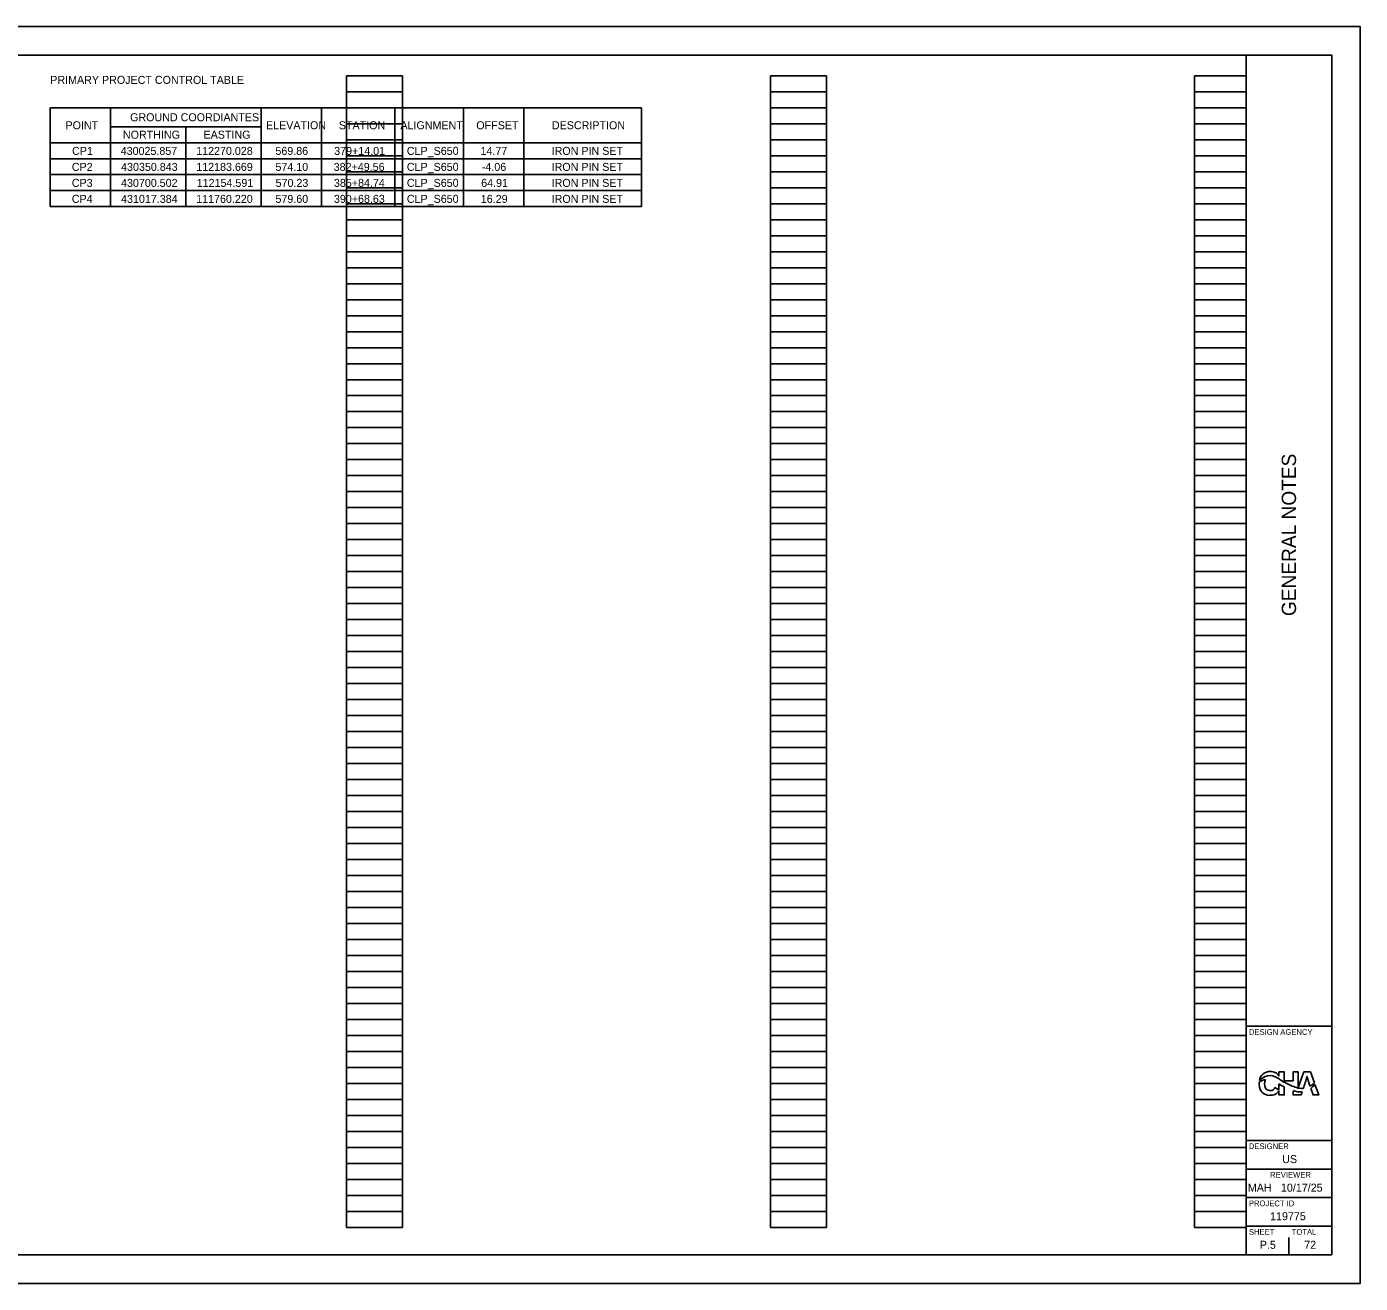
# Model space of a CAD drawing. Extents: x -7.3 to 34, y 0 to 22.
# Drawn here: x 10.66 to 34, y 0 to 22 of the extents above; entities that cross this region are included whole.
import ezdxf

# ---------------------------------------------------------------- set-up
doc = ezdxf.new("R2010")
doc.units = 0
for name, color, linetype in [('Default', 7, 'Continuous'), ('SH_Border', 7, 'Continuous'), ('SH_Cut_Line', 7, 'Continuous'), ('SH_Data', 7, 'Continuous'), ('SH_Text', 7, 'Continuous')]:
    doc.layers.add(name, color=color, linetype=linetype)

msp = doc.modelspace()

# ---------------------------------------------------------------- linework, layer by layer
at = {"layer": 'Default'}
for p, q in [((11.078, 20.578), (21.421, 20.578)), ((11.078, 20.578), (11.078, 18.849)), ((12.132, 20.578), (12.132, 18.849)), ((14.767, 20.578), (14.767, 18.849)), ((15.821, 20.578), (15.821, 18.849)), ((17.106, 20.578), (17.106, 18.849)), ((18.308, 20.578), (18.308, 18.849)), ((19.362, 20.578), (19.362, 18.849)), ((21.421, 20.578), (21.421, 18.849)), ((12.132, 20.249), (14.767, 20.249)), ((13.449, 20.249), (13.449, 18.849)), ((11.078, 19.969), (21.421, 19.969)), ((11.078, 19.689), (21.421, 19.689)), ((11.078, 19.409), (21.421, 19.409)), ((11.078, 19.129), (21.421, 19.129)), ((11.078, 18.849), (21.421, 18.849))]:
    msp.add_line(p, q, dxfattribs=at)
at = {"layer": 'SH_Border'}
for p, q in [((32, 0.5), (32, 21.5)), ((32, 4.5), (33.5, 4.5)), ((32, 2.5), (33.5, 2.5)), ((32, 2), (33.5, 2)), ((32, 1.5), (33.5, 1.5)), ((32, 1), (33.5, 1))]:
    msp.add_line(p, q, dxfattribs=at)
msp.add_lwpolyline([(1.5, 21.5), (33.5, 21.5), (33.5, 0.5), (1.5, 0.5)], close=True, dxfattribs=at)
at = {"layer": 'SH_Cut_Line'}
msp.add_lwpolyline([(0, 0), (34, 0), (34, 22), (0, 22)], close=True, dxfattribs=at)
at = {"layer": 'SH_Data'}
for p, q in [((16.26, 0.98), (16.26, 21.14)), ((16.26, 21.14), (17.24, 21.14)), ((17.24, 0.98), (17.24, 21.14)), ((23.68, 0.98), (23.68, 21.14)), ((23.68, 21.14), (24.66, 21.14)), ((24.66, 0.98), (24.66, 21.14)), ((31.1, 0.98), (31.1, 21.14)), ((31.1, 21.14), (32, 21.14)), ((32, 0.98), (32, 21.14)), ((16.26, 20.86), (17.24, 20.86)), ((23.68, 20.86), (24.66, 20.86)), ((31.1, 20.86), (32, 20.86)), ((16.26, 20.58), (17.24, 20.58)), ((23.68, 20.58), (24.66, 20.58)), ((31.1, 20.58), (32, 20.58)), ((16.26, 20.3), (17.24, 20.3)), ((23.68, 20.3), (24.66, 20.3)), ((31.1, 20.3), (32, 20.3)), ((16.26, 20.02), (17.24, 20.02)), ((23.68, 20.02), (24.66, 20.02)), ((31.1, 20.02), (32, 20.02)), ((16.26, 19.74), (17.24, 19.74)), ((23.68, 19.74), (24.66, 19.74)), ((31.1, 19.74), (32, 19.74)), ((16.26, 19.46), (17.24, 19.46)), ((23.68, 19.46), (24.66, 19.46)), ((31.1, 19.46), (32, 19.46)), ((16.26, 19.18), (17.24, 19.18)), ((23.68, 19.18), (24.66, 19.18)), ((31.1, 19.18), (32, 19.18)), ((16.26, 18.9), (17.24, 18.9)), ((23.68, 18.9), (24.66, 18.9)), ((31.1, 18.9), (32, 18.9)), ((16.26, 18.62), (17.24, 18.62)), ((23.68, 18.62), (24.66, 18.62)), ((31.1, 18.62), (32, 18.62)), ((16.26, 18.34), (17.24, 18.34)), ((23.68, 18.34), (24.66, 18.34)), ((31.1, 18.34), (32, 18.34)), ((16.26, 18.06), (17.24, 18.06)), ((23.68, 18.06), (24.66, 18.06)), ((31.1, 18.06), (32, 18.06)), ((16.26, 17.78), (17.24, 17.78)), ((23.68, 17.78), (24.66, 17.78)), ((31.1, 17.78), (32, 17.78)), ((16.26, 17.5), (17.24, 17.5)), ((23.68, 17.5), (24.66, 17.5)), ((31.1, 17.5), (32, 17.5)), ((16.26, 17.22), (17.24, 17.22)), ((23.68, 17.22), (24.66, 17.22)), ((31.1, 17.22), (32, 17.22)), ((16.26, 16.94), (17.24, 16.94)), ((23.68, 16.94), (24.66, 16.94)), ((31.1, 16.94), (32, 16.94)), ((16.26, 16.66), (17.24, 16.66)), ((23.68, 16.66), (24.66, 16.66)), ((31.1, 16.66), (32, 16.66)), ((16.26, 16.38), (17.24, 16.38)), ((23.68, 16.38), (24.66, 16.38)), ((31.1, 16.38), (32, 16.38)), ((16.26, 16.1), (17.24, 16.1)), ((23.68, 16.1), (24.66, 16.1)), ((31.1, 16.1), (32, 16.1)), ((16.26, 15.82), (17.24, 15.82)), ((23.68, 15.82), (24.66, 15.82)), ((31.1, 15.82), (32, 15.82)), ((16.26, 15.54), (17.24, 15.54)), ((23.68, 15.54), (24.66, 15.54)), ((31.1, 15.54), (32, 15.54)), ((16.26, 15.26), (17.24, 15.26)), ((23.68, 15.26), (24.66, 15.26)), ((31.1, 15.26), (32, 15.26)), ((16.26, 14.98), (17.24, 14.98)), ((23.68, 14.98), (24.66, 14.98)), ((31.1, 14.98), (32, 14.98)), ((16.26, 14.7), (17.24, 14.7)), ((23.68, 14.7), (24.66, 14.7)), ((31.1, 14.7), (32, 14.7)), ((16.26, 14.42), (17.24, 14.42)), ((23.68, 14.42), (24.66, 14.42)), ((31.1, 14.42), (32, 14.42)), ((16.26, 14.14), (17.24, 14.14)), ((23.68, 14.14), (24.66, 14.14)), ((31.1, 14.14), (32, 14.14)), ((16.26, 13.86), (17.24, 13.86)), ((23.68, 13.86), (24.66, 13.86)), ((31.1, 13.86), (32, 13.86)), ((16.26, 13.58), (17.24, 13.58)), ((23.68, 13.58), (24.66, 13.58)), ((31.1, 13.58), (32, 13.58)), ((16.26, 13.3), (17.24, 13.3)), ((23.68, 13.3), (24.66, 13.3)), ((31.1, 13.3), (32, 13.3)), ((16.26, 13.02), (17.24, 13.02)), ((23.68, 13.02), (24.66, 13.02)), ((31.1, 13.02), (32, 13.02)), ((16.26, 12.74), (17.24, 12.74)), ((23.68, 12.74), (24.66, 12.74)), ((31.1, 12.74), (32, 12.74)), ((16.26, 12.46), (17.24, 12.46)), ((23.68, 12.46), (24.66, 12.46)), ((31.1, 12.46), (32, 12.46)), ((16.26, 12.18), (17.24, 12.18)), ((23.68, 12.18), (24.66, 12.18)), ((31.1, 12.18), (32, 12.18)), ((16.26, 11.9), (17.24, 11.9)), ((23.68, 11.9), (24.66, 11.9)), ((31.1, 11.9), (32, 11.9)), ((16.26, 11.62), (17.24, 11.62)), ((23.68, 11.62), (24.66, 11.62)), ((31.1, 11.62), (32, 11.62)), ((16.26, 11.34), (17.24, 11.34)), ((23.68, 11.34), (24.66, 11.34)), ((31.1, 11.34), (32, 11.34)), ((16.26, 11.06), (17.24, 11.06)), ((23.68, 11.06), (24.66, 11.06)), ((31.1, 11.06), (32, 11.06)), ((16.26, 10.78), (17.24, 10.78)), ((23.68, 10.78), (24.66, 10.78)), ((31.1, 10.78), (32, 10.78)), ((16.26, 10.5), (17.24, 10.5)), ((23.68, 10.5), (24.66, 10.5)), ((31.1, 10.5), (32, 10.5)), ((16.26, 10.22), (17.24, 10.22)), ((23.68, 10.22), (24.66, 10.22)), ((31.1, 10.22), (32, 10.22)), ((16.26, 9.94), (17.24, 9.94)), ((23.68, 9.94), (24.66, 9.94)), ((31.1, 9.94), (32, 9.94)), ((16.26, 9.66), (17.24, 9.66)), ((23.68, 9.66), (24.66, 9.66)), ((31.1, 9.66), (32, 9.66)), ((16.26, 9.38), (17.24, 9.38)), ((23.68, 9.38), (24.66, 9.38)), ((31.1, 9.38), (32, 9.38)), ((16.26, 9.1), (17.24, 9.1)), ((23.68, 9.1), (24.66, 9.1)), ((31.1, 9.1), (32, 9.1)), ((16.26, 8.82), (17.24, 8.82)), ((23.68, 8.82), (24.66, 8.82)), ((31.1, 8.82), (32, 8.82)), ((16.26, 8.54), (17.24, 8.54)), ((23.68, 8.54), (24.66, 8.54)), ((31.1, 8.54), (32, 8.54)), ((16.26, 8.26), (17.24, 8.26)), ((23.68, 8.26), (24.66, 8.26)), ((31.1, 8.26), (32, 8.26)), ((16.26, 7.98), (17.24, 7.98)), ((23.68, 7.98), (24.66, 7.98)), ((31.1, 7.98), (32, 7.98)), ((16.26, 7.7), (17.24, 7.7)), ((23.68, 7.7), (24.66, 7.7)), ((31.1, 7.7), (32, 7.7)), ((16.26, 7.42), (17.24, 7.42)), ((23.68, 7.42), (24.66, 7.42)), ((31.1, 7.42), (32, 7.42)), ((16.26, 7.14), (17.24, 7.14)), ((23.68, 7.14), (24.66, 7.14)), ((31.1, 7.14), (32, 7.14)), ((16.26, 6.86), (17.24, 6.86)), ((23.68, 6.86), (24.66, 6.86)), ((31.1, 6.86), (32, 6.86)), ((16.26, 6.58), (17.24, 6.58)), ((23.68, 6.58), (24.66, 6.58)), ((31.1, 6.58), (32, 6.58)), ((16.26, 6.3), (17.24, 6.3)), ((23.68, 6.3), (24.66, 6.3)), ((31.1, 6.3), (32, 6.3)), ((16.26, 6.02), (17.24, 6.02)), ((23.68, 6.02), (24.66, 6.02)), ((31.1, 6.02), (32, 6.02)), ((16.26, 5.74), (17.24, 5.74)), ((23.68, 5.74), (24.66, 5.74)), ((31.1, 5.74), (32, 5.74)), ((16.26, 5.46), (17.24, 5.46)), ((23.68, 5.46), (24.66, 5.46)), ((31.1, 5.46), (32, 5.46)), ((16.26, 5.18), (17.24, 5.18)), ((23.68, 5.18), (24.66, 5.18)), ((31.1, 5.18), (32, 5.18)), ((16.26, 4.9), (17.24, 4.9)), ((23.68, 4.9), (24.66, 4.9)), ((31.1, 4.9), (32, 4.9)), ((16.26, 4.62), (17.24, 4.62)), ((23.68, 4.62), (24.66, 4.62)), ((31.1, 4.62), (32, 4.62)), ((16.26, 4.34), (17.24, 4.34)), ((23.68, 4.34), (24.66, 4.34)), ((31.1, 4.34), (32, 4.34)), ((16.26, 4.06), (17.24, 4.06)), ((23.68, 4.06), (24.66, 4.06)), ((31.1, 4.06), (32, 4.06)), ((16.26, 3.78), (17.24, 3.78)), ((23.68, 3.78), (24.66, 3.78)), ((31.1, 3.78), (32, 3.78)), ((16.26, 3.5), (17.24, 3.5)), ((23.68, 3.5), (24.66, 3.5)), ((31.1, 3.5), (32, 3.5)), ((32.75, 3.5), (32.75, 3.5)), ((16.26, 3.22), (17.24, 3.22)), ((23.68, 3.22), (24.66, 3.22)), ((31.1, 3.22), (32, 3.22)), ((16.26, 2.94), (17.24, 2.94)), ((23.68, 2.94), (24.66, 2.94)), ((31.1, 2.94), (32, 2.94)), ((16.26, 2.66), (17.24, 2.66)), ((23.68, 2.66), (24.66, 2.66)), ((31.1, 2.66), (32, 2.66)), ((16.26, 2.38), (17.24, 2.38)), ((23.68, 2.38), (24.66, 2.38)), ((31.1, 2.38), (32, 2.38)), ((16.26, 2.1), (17.24, 2.1)), ((23.68, 2.1), (24.66, 2.1)), ((31.1, 2.1), (32, 2.1)), ((16.26, 1.82), (17.24, 1.82)), ((23.68, 1.82), (24.66, 1.82)), ((31.1, 1.82), (32, 1.82)), ((16.26, 1.54), (17.24, 1.54)), ((23.68, 1.54), (24.66, 1.54)), ((31.1, 1.54), (32, 1.54)), ((16.26, 1.26), (17.24, 1.26)), ((23.68, 1.26), (24.66, 1.26)), ((31.1, 1.26), (32, 1.26)), ((16.26, 0.98), (17.24, 0.98)), ((23.68, 0.98), (24.66, 0.98)), ((31.1, 0.98), (32, 0.98)), ((32.75, 0.5), (32.75, 0.8)), ((32.375, 0.675), (32.375, 0.675))]:
    msp.add_line(p, q, dxfattribs=at)
at = {"layer": 'SH_Text'}
msp.add_line((33.066, 3.619), (33.069, 3.619), dxfattribs=at)
for points in [[(33.196, 3.508), (33.126, 3.7), (33.012, 3.7), (32.915, 3.431), (32.915, 3.7), (32.822, 3.7), (32.822, 3.543), (32.669, 3.543), (32.669, 3.7), (32.576, 3.7), (32.576, 3.629)], [(32.576, 3.492), (32.576, 3.389), (32.507, 3.43)], [(32.576, 3.37), (32.576, 3.3), (32.669, 3.3), (32.669, 3.439)], [(32.822, 3.373), (32.822, 3.3), (32.867, 3.3), (32.915, 3.3), (32.964, 3.3), (32.981, 3.351)], [(33.133, 3.413), (33.144, 3.383), (33.173, 3.3), (33.272, 3.3), (33.206, 3.481)]]:
    msp.add_lwpolyline(points, dxfattribs=at)
for centre, radius, start, end in [((32.471, 3.495), 0.242, 173.6843, 214.2778), ((32.441, 3.209), 0.376, 105.7483, 123.9538), ((32.414, 3.529), 0.181, 129.6629, 172.5664), ((32.505, 3.249), 0.407, 114.8364, 131.7457), ((32.418, 3.503), 0.205, 88.0817, 126.0325), ((32.516, 3.499), 0.192, 157.8882, 204.8663), ((32.417, 3.436), 0.201, 63.1724, 114.4396), ((32.43, 3.514), 0.194, 64.9016, 91.2438), ((32.183, 2.916), 0.771, 57.2913, 65.1), ((32.442, 3.551), 0.155, 30.3756, 63.3712), ((33.592, 5.1), 1.829, 237.1308, 240.4227), ((33.204, 4.445), 1.067, 241.1998, 252.5446), ((31.298, 4.056), 1.821, 339.3263, 346.125), ((34.073, 3.831), 1.026, 191.9132, 201.6837), ((32.877, 3.865), 0.479, 300.42, 311.7894), ((32.347, 3.41), 0.0923, 214.2778, 222.6269), ((32.407, 3.465), 0.174, 222.6269, 271.9347), ((32.404, 3.447), 0.0681, 204.8663, 223.055), ((32.418, 3.46), 0.0871, 223.055, 273.5972), ((32.423, 3.511), 0.219, 267.5421, 292.3552), ((32.424, 3.461), 0.0879, 269.2163, 339.4439), ((32.441, 3.453), 0.159, 294.1165, 328.289), ((33.232, 4.512), 1.213, 237.2686, 242.3197), ((32.953, 3.737), 0.386, 250.2087, 274.1935), ((32.979, 3.72), 0.308, 251.9229, 274.261), ((32.822, 3.823), 0.515, 307.219, 318.2934)]:
    msp.add_arc(centre, radius, start, end, dxfattribs=at)

# ---------------------------------------------------------------- texts
at = {"layer": 'Default'}
for s, p in [('POINT', (11.344, 20.204)), ('GROUND COORDIANTES', (12.475, 20.344)), ('ELEVATION', (14.852, 20.204)), ('STATION', (16.127, 20.204)), ('ALIGNMENT', (17.204, 20.204)), ('OFFSET', (18.532, 20.204)), ('DESCRIPTION', (19.855, 20.204)), ('NORTHING', (12.349, 20.039)), ('EASTING', (13.76, 20.039)), ('CP1', (11.46, 19.755)), ('430025.857', (12.31, 19.755)), ('112270.028', (13.631, 19.755)), ('569.86', (15.017, 19.755)), ('379+14.01', (16.046, 19.755)), ('CLP_S650', (17.317, 19.755)), ('14.77', (18.606, 19.755)), ('IRON PIN SET', (19.851, 19.755)), ('CP2', (11.455, 19.475)), ('430350.843', (12.317, 19.475)), ('112183.669', (13.632, 19.475)), ('574.10', (15.018, 19.475)), ('382+49.56', (16.037, 19.475)), ('CLP_S650', (17.317, 19.475)), ('-4.06', (18.629, 19.475)), ('IRON PIN SET', (19.851, 19.475)), ('CP3', (11.455, 19.195)), ('430700.502', (12.316, 19.195)), ('112154.591', (13.64, 19.195)), ('570.23', (15.021, 19.195)), ('385+84.74', (16.041, 19.195)), ('CLP_S650', (17.317, 19.195)), ('64.91', (18.618, 19.195)), ('IRON PIN SET', (19.851, 19.195)), ('CP4', (11.455, 18.915)), ('431017.384', (12.317, 18.915)), ('111760.220', (13.631, 18.915)), ('579.60', (15.018, 18.915)), ('390+68.63', (16.041, 18.915)), ('CLP_S650', (17.317, 18.915)), ('16.29', (18.611, 18.915)), ('IRON PIN SET', (19.851, 18.915))]:
    msp.add_text(s, height=0.14, dxfattribs=at).set_placement(p)
at = {"layer": 'SH_Data'}
msp.add_text('GENERAL NOTES', height=0.25, rotation=90, dxfattribs=at).set_placement((32.875, 11.682))
for s, height, p in [('DESIGN AGENCY', 0.1, (32.05, 4.35)), ('DESIGNER', 0.1, (32.05, 2.35)), ('US', 0.14, (32.633, 2.105)), ('REVIEWER', 0.1, (32.422, 1.85)), ('MAH', 0.14, (32.032, 1.605)), ('10/17/25', 0.14, (32.611, 1.605)), ('PROJECT ID', 0.1, (32.05, 1.35)), ('119775', 0.14, (32.421, 1.105)), ('SHEET', 0.1, (32.05, 0.85)), ('TOTAL', 0.1, (32.8, 0.85)), ('P.5', 0.14, (32.241, 0.605)), ('72', 0.14, (33.019, 0.605))]:
    msp.add_text(s, height=height, dxfattribs=at).set_placement(p)
at = {"layer": 'SH_Text'}
msp.add_text('PRIMARY PROJECT CONTROL TABLE', height=0.14, dxfattribs=at).set_placement((11.078, 20.998))

doc.saveas('drawing.dxf')
